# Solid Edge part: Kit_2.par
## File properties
Sűrűség: 0,000 kg/m^3
Pontosság: 0,990
Author: bmolnar
Last saved by: bmolnar
Revision: 77
Username: bmolnar
Dokumentum tartalom típus: 0
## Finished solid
Body 1: solid body, 22 faces, 38 edges, 28 vertices.
  Faces by surface: cylinder 10, plane 9, cone 2, torus 1
  Edges by curve: circle 24, line 14
Bounding box of the edges (mm; curved faces can reach further): 106.000 x 105.975 x 9.950, from (-53, -50.85, 0.95) to (53, 55.125, 10.9).
Cylindrical faces by radius (mm): R1.75 x2, R3.5 x4, R40 x1, R46.625 x1, R50.85 x1, R53 x1
Conical faces (half-angle, radius in mm at the cone's reference point): 45 deg R39.5 x1, 45 deg R50.8 x1
Toroidal faces (ring radius, tube radius in mm): R40.8 r0.8 x1
Planar faces by outward normal: +z 2, -z 5, oblique 2
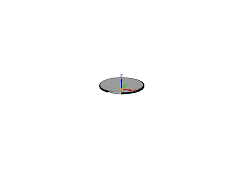
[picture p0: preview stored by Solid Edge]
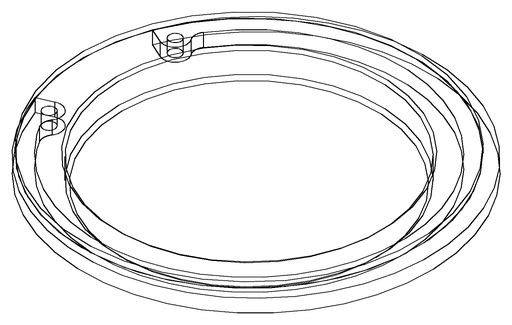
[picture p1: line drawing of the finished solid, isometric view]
